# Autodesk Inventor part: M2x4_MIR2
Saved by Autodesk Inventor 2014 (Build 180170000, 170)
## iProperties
Created: 2015-05
Part Number: M2x4_MIR2
Material: 일반
Vendor: CBT Solutions
Document SubType Name: 모델링
Designer: Administrator
Appearance: 기본값
Company: 한국ATC센터
Author: KYOUNG IL JANG
Comments: 파생
d0: 1.000 ul
d0_1: 1.000 ul
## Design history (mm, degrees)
derived "M2x4.ipt" dims count "d0" = 1
feature "솔리드1::M2x4.ipt" dims count "d0" = 1
tag "피쳐 태그1"
node "솔리드1"
other parameters: "d0_1" = 1
